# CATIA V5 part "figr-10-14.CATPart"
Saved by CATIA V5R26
Part number: Part1
Bounding box of the stored display mesh (mm): x 0 to 0, y -7.819 to 219.529, z -24.144 to 176.857
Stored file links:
  D:\_Deepak\CATIA\CATIA V5-6R2016_Deepak\Resources\Part files\Partfiles\c10_catia_v5_6r2016_prt\figr-10-14.CATPart
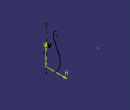
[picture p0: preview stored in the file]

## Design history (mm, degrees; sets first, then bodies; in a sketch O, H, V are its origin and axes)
Set1
  Sketch1 on yz-plane, origin (0, 0, 0), H (0, 1, 0), V (0, 0, 1)
    arc A1 centre (219.5293, 176.8574) radius 194.8379 from (50.3627, 80.1907) to (30.3627, 130.1907) cw
    arc A2 centre (-7.8186, 46.9443) radius 67.0103 from (50.3627, 80.1907) to (40, 0) cw
    arc A3 centre (47.0688, 134.312) radius 17.207 from (30.3627, 130.1907) to (40, 150) cw
    axis line L1 (0, 156.5671) -> (0, -24.1442)
    vertical: L1 V
  Revol1: Element1 Sketch1, Angle1 -60
Body1 (main body)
